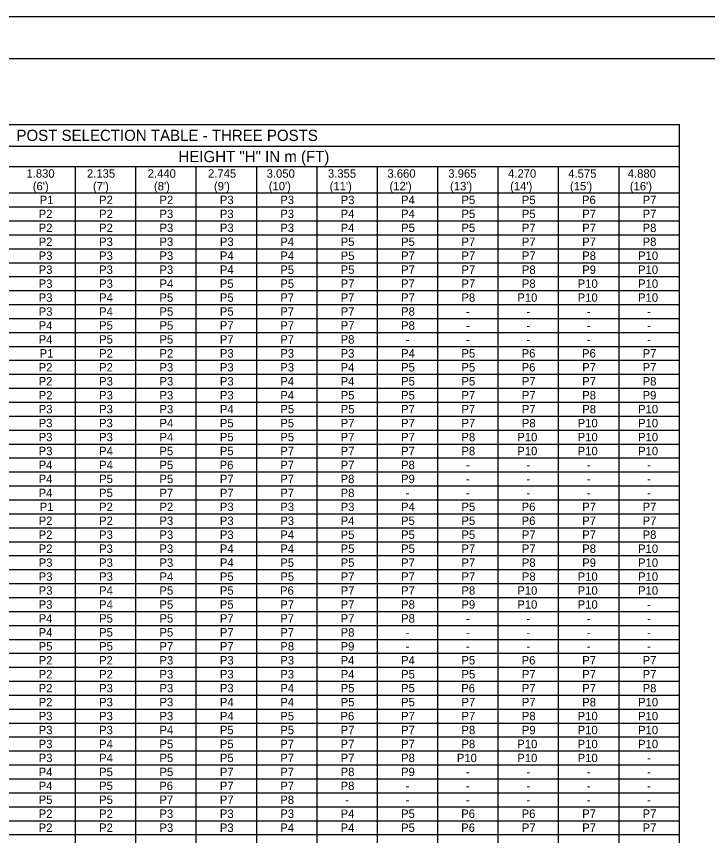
# Model space of a CAD drawing. Extents: x 637580 to 641008, y 294594 to 295782.
# Drawn here: x 640290.4 to 640536.7, y 295489.6 to 295781.6 of the extents above; entities that cross this region are included whole.
import ezdxf

# ---------------------------------------------------------------- set-up
doc = ezdxf.new("R2010")
doc.units = 0
for name, color, linetype in [('1', 7, 'Continuous'), ('2', 7, 'Continuous'), ('PLT-BNDY', 7, 'Continuous')]:
    doc.layers.add(name, color=color, linetype=linetype)

msp = doc.modelspace()

# ---------------------------------------------------------------- linework, layer by layer
at = {"layer": '1'}
for p, q in [((640143.31, 295766.63), (640929.31, 295766.63)), ((640191.43, 295743.08), (640526.66, 295743.08)), ((640526.66, 295226.43), (640526.66, 295743.08)), ((640191.43, 295735.41), (640526.66, 295735.41)), ((640191.43, 295718.7), (640526.66, 295718.7)), ((640191.43, 295664.01), (640526.66, 295664.01)), ((640191.43, 295609.31), (640526.66, 295609.31)), ((640191.43, 295554.61), (640526.66, 295554.61)), ((640191.43, 295499.91), (640526.66, 295499.91))]:
    msp.add_line(p, q, dxfattribs=at)
at = {"layer": '2'}
for p, q in [((640246.95, 295728.06), (640526.66, 295728.06)), ((640311.5, 295226.43), (640311.5, 295728.06)), ((640333.02, 295226.43), (640333.02, 295728.06)), ((640354.53, 295226.43), (640354.53, 295728.06)), ((640376.05, 295226.43), (640376.05, 295728.06)), ((640397.56, 295226.43), (640397.56, 295728.06)), ((640419.08, 295226.43), (640419.08, 295728.06)), ((640440.6, 295226.43), (640440.6, 295728.06)), ((640462.11, 295226.43), (640462.11, 295728.06)), ((640483.63, 295226.43), (640483.63, 295728.06)), ((640505.14, 295226.43), (640505.14, 295728.06)), ((640211.96, 295718.7), (640526.66, 295718.7)), ((640218.95, 295713.73), (640526.66, 295713.73)), ((640218.95, 295708.76), (640526.66, 295708.76)), ((640218.95, 295703.79), (640526.66, 295703.79)), ((640218.95, 295698.81), (640526.66, 295698.81)), ((640218.95, 295693.84), (640526.66, 295693.84)), ((640218.95, 295688.87), (640526.66, 295688.87)), ((640218.95, 295683.9), (640526.66, 295683.9)), ((640218.95, 295678.92), (640526.66, 295678.92)), ((640218.95, 295673.95), (640526.66, 295673.95)), ((640218.95, 295668.98), (640526.66, 295668.98)), ((640218.95, 295659.03), (640526.66, 295659.03)), ((640218.95, 295654.06), (640526.66, 295654.06)), ((640218.95, 295649.09), (640526.66, 295649.09)), ((640218.95, 295644.12), (640526.66, 295644.12)), ((640218.95, 295639.14), (640526.66, 295639.14)), ((640218.95, 295634.17), (640526.66, 295634.17)), ((640218.95, 295629.2), (640526.66, 295629.2)), ((640218.95, 295624.23), (640526.66, 295624.23)), ((640218.95, 295619.25), (640526.66, 295619.25)), ((640218.95, 295614.28), (640526.66, 295614.28)), ((640218.95, 295604.34), (640526.66, 295604.34)), ((640218.95, 295599.36), (640526.66, 295599.36)), ((640218.95, 295594.39), (640526.66, 295594.39)), ((640218.95, 295589.42), (640526.66, 295589.42)), ((640218.95, 295584.45), (640526.66, 295584.45)), ((640218.95, 295579.47), (640526.66, 295579.47)), ((640218.95, 295574.5), (640526.66, 295574.5)), ((640218.95, 295569.53), (640526.66, 295569.53)), ((640218.95, 295564.56), (640526.66, 295564.56)), ((640218.95, 295559.58), (640526.66, 295559.58)), ((640218.95, 295549.64), (640526.66, 295549.64)), ((640218.95, 295544.67), (640526.66, 295544.67)), ((640218.95, 295539.69), (640526.66, 295539.69)), ((640218.95, 295534.72), (640526.66, 295534.72)), ((640218.95, 295529.75), (640526.66, 295529.75)), ((640218.95, 295524.78), (640526.66, 295524.78)), ((640218.95, 295519.8), (640526.66, 295519.8)), ((640218.95, 295514.83), (640526.66, 295514.83)), ((640218.95, 295509.86), (640526.66, 295509.86)), ((640218.95, 295504.89), (640526.66, 295504.89)), ((640218.95, 295494.94), (640526.66, 295494.94)), ((640218.95, 295489.97), (640526.66, 295489.97))]:
    msp.add_line(p, q, dxfattribs=at)
at = {"layer": 'PLT-BNDY'}
msp.add_lwpolyline([(640103.31, 295781.63), (640944.31, 295781.63), (640944.31, 295187.63), (640103.31, 295187.63)], close=True, dxfattribs=at)

# ---------------------------------------------------------------- texts
at = {"layer": '1'}
for s, height, p in [('POST SELECTION TABLE - THREE POSTS', 4.003, (640290.47, 295737.22)), ('HEIGHT "H" IN m (FT)', 4.003, (640348.19, 295729.67)), ('1.830', 3, (640294.03, 295724.12)), ('2.135', 3, (640315.59, 295724.12)), ('2.440', 3, (640337.22, 295724.12)), ('2.745', 3, (640358.71, 295724.12)), ('3.050', 3, (640379.6, 295724.12)), ('3.355', 3, (640401.43, 295724.12)), ('3.660', 3, (640422.63, 295724.12)), ('3.965', 3, (640444.31, 295724.12)), ('4.270', 3, (640465.6, 295724.12)), ('4.575', 3, (640487.05, 295724.12)), ('4.880', 3, (640508.25, 295724.12)), ("(6')", 3, (640296.28, 295719.62)), ("(7')", 3, (640317.71, 295719.62)), ("(8')", 3, (640339.47, 295719.62)), ("(9')", 3, (640360.83, 295719.62)), ("(10')", 3, (640380.34, 295719.62)), ("(11')", 3, (640402.05, 295719.62)), ("(12')", 3, (640423.37, 295719.62)), ("(13')", 3, (640444.93, 295719.62)), ("(14')", 3, (640466.34, 295719.62)), ("(15')", 3, (640487.67, 295719.62)), ("(16')", 3, (640508.99, 295719.62)), ('P1', 3, (640298.74, 295714.72)), ('P2', 3, (640319.91, 295714.72)), ('P2', 3, (640341.42, 295714.72)), ('P3', 3, (640362.94, 295714.72)), ('P3', 3, (640384.46, 295714.72)), ('P3', 3, (640405.97, 295714.71)), ('P4', 3, (640427.49, 295714.72)), ('P5', 3, (640449, 295714.72)), ('P5', 3, (640470.52, 295714.72)), ('P6', 3, (640491.95, 295714.72)), ('P7', 3, (640513.55, 295714.72)), ('P2', 3, (640298.39, 295709.74)), ('P2', 3, (640319.91, 295709.74)), ('P3', 3, (640341.42, 295709.74)), ('P3', 3, (640362.94, 295709.74)), ('P3', 3, (640384.46, 295709.74)), ('P4', 3, (640405.97, 295709.74)), ('P4', 3, (640427.49, 295709.74)), ('P5', 3, (640449, 295709.74)), ('P5', 3, (640470.52, 295709.74)), ('P7', 3, (640492.03, 295709.74)), ('P7', 3, (640513.55, 295709.74)), ('P2', 3, (640298.39, 295704.77)), ('P2', 3, (640319.91, 295704.77)), ('P3', 3, (640341.42, 295704.77)), ('P3', 3, (640362.94, 295704.77)), ('P3', 3, (640384.46, 295704.77)), ('P4', 3, (640405.97, 295704.77)), ('P5', 3, (640427.49, 295704.77)), ('P5', 3, (640449, 295704.77)), ('P7', 3, (640470.52, 295704.77)), ('P7', 3, (640492.03, 295704.77)), ('P8', 3, (640513.55, 295704.77)), ('P2', 3, (640298.39, 295699.8)), ('P3', 3, (640319.91, 295699.8)), ('P3', 3, (640341.42, 295699.8)), ('P3', 3, (640362.94, 295699.8)), ('P4', 3, (640384.46, 295699.8)), ('P5', 3, (640405.97, 295699.79)), ('P5', 3, (640427.49, 295699.8)), ('P7', 3, (640449, 295699.8)), ('P7', 3, (640470.52, 295699.8)), ('P7', 3, (640492.03, 295699.8)), ('P8', 3, (640513.55, 295699.8)), ('P3', 3, (640298.39, 295694.83)), ('P3', 3, (640319.91, 295694.83)), ('P3', 3, (640341.42, 295694.83)), ('P4', 3, (640362.94, 295694.83)), ('P4', 3, (640384.46, 295694.83)), ('P5', 3, (640405.97, 295694.82)), ('P7', 3, (640427.49, 295694.83)), ('P7', 3, (640449, 295694.83)), ('P7', 3, (640470.52, 295694.83)), ('P8', 3, (640492.03, 295694.83)), ('P10', 3, (640511.92, 295694.83)), ('P3', 3, (640298.39, 295689.85)), ('P3', 3, (640319.91, 295689.85)), ('P3', 3, (640341.42, 295689.85)), ('P4', 3, (640362.94, 295689.85)), ('P5', 3, (640384.46, 295689.85)), ('P5', 3, (640405.97, 295689.85)), ('P7', 3, (640427.49, 295689.85)), ('P7', 3, (640449, 295689.85)), ('P8', 3, (640470.52, 295689.85)), ('P9', 3, (640492.02, 295689.85)), ('P10', 3, (640511.92, 295689.85)), ('P3', 3, (640298.39, 295684.88)), ('P3', 3, (640319.91, 295684.88)), ('P4', 3, (640341.42, 295684.88)), ('P5', 3, (640362.94, 295684.88)), ('P5', 3, (640384.46, 295684.88)), ('P7', 3, (640405.97, 295684.88)), ('P7', 3, (640427.49, 295684.88)), ('P7', 3, (640449, 295684.88)), ('P8', 3, (640470.52, 295684.88)), ('P10', 3, (640490.4, 295684.88)), ('P10', 3, (640511.92, 295684.88)), ('P3', 3, (640298.39, 295679.91)), ('P4', 3, (640319.91, 295679.91)), ('P5', 3, (640341.42, 295679.91)), ('P5', 3, (640362.94, 295679.91)), ('P7', 3, (640384.46, 295679.91)), ('P7', 3, (640405.97, 295679.9)), ('P7', 3, (640427.49, 295679.91)), ('P8', 3, (640449, 295679.91)), ('P10', 3, (640468.89, 295679.91)), ('P10', 3, (640490.4, 295679.91)), ('P10', 3, (640511.92, 295679.91)), ('P3', 3, (640298.39, 295674.94)), ('P4', 3, (640319.91, 295674.94)), ('P5', 3, (640341.42, 295674.94)), ('P5', 3, (640362.94, 295674.94)), ('P7', 3, (640384.46, 295674.94)), ('P7', 3, (640405.97, 295674.93)), ('P8', 3, (640427.49, 295674.94)), ('-', 3, (640450.62, 295674.94)), ('-', 3, (640472.14, 295674.94)), ('-', 3, (640493.65, 295674.94)), ('-', 3, (640515.17, 295674.94)), ('P4', 3, (640298.39, 295669.96)), ('P5', 3, (640319.91, 295669.96)), ('P5', 3, (640341.42, 295669.96)), ('P7', 3, (640362.94, 295669.96)), ('P7', 3, (640384.46, 295669.96)), ('P7', 3, (640405.97, 295669.96)), ('P8', 3, (640427.49, 295669.96)), ('-', 3, (640450.62, 295669.96)), ('-', 3, (640472.14, 295669.96)), ('-', 3, (640493.65, 295669.96)), ('-', 3, (640515.17, 295669.96)), ('P4', 3, (640298.39, 295664.99)), ('P5', 3, (640319.91, 295664.99)), ('P5', 3, (640341.42, 295664.99)), ('P7', 3, (640362.94, 295664.99)), ('P7', 3, (640384.46, 295664.99)), ('P8', 3, (640405.97, 295664.99)), ('-', 3, (640429.11, 295664.99)), ('-', 3, (640450.62, 295664.99)), ('-', 3, (640472.14, 295664.99)), ('-', 3, (640493.65, 295664.99)), ('-', 3, (640515.17, 295664.99)), ('P1', 3, (640298.74, 295660.02)), ('P2', 3, (640319.91, 295660.02)), ('P2', 3, (640341.42, 295660.02)), ('P3', 3, (640362.94, 295660.02)), ('P3', 3, (640384.46, 295660.02)), ('P3', 3, (640405.97, 295660.01)), ('P4', 3, (640427.49, 295660.02)), ('P5', 3, (640449, 295660.02)), ('P6', 3, (640470.44, 295660.02)), ('P6', 3, (640491.95, 295660.02)), ('P7', 3, (640513.55, 295660.02)), ('P2', 3, (640298.39, 295655.05)), ('P2', 3, (640319.91, 295655.05)), ('P3', 3, (640341.42, 295655.05)), ('P3', 3, (640362.94, 295655.05)), ('P3', 3, (640384.46, 295655.05)), ('P4', 3, (640405.97, 295655.04)), ('P5', 3, (640427.49, 295655.05)), ('P5', 3, (640449, 295655.05)), ('P6', 3, (640470.44, 295655.05)), ('P7', 3, (640492.03, 295655.05)), ('P7', 3, (640513.55, 295655.05)), ('P2', 3, (640298.39, 295650.07)), ('P3', 3, (640319.91, 295650.07)), ('P3', 3, (640341.42, 295650.07)), ('P3', 3, (640362.94, 295650.07)), ('P4', 3, (640384.46, 295650.07)), ('P4', 3, (640405.97, 295650.07)), ('P5', 3, (640427.49, 295650.07)), ('P5', 3, (640449, 295650.07)), ('P7', 3, (640470.52, 295650.07)), ('P7', 3, (640492.03, 295650.07)), ('P8', 3, (640513.55, 295650.07)), ('P2', 3, (640298.39, 295645.1)), ('P3', 3, (640319.91, 295645.1)), ('P3', 3, (640341.42, 295645.1)), ('P3', 3, (640362.94, 295645.1)), ('P4', 3, (640384.46, 295645.1)), ('P5', 3, (640405.97, 295645.1)), ('P5', 3, (640427.49, 295645.1)), ('P7', 3, (640449, 295645.1)), ('P7', 3, (640470.52, 295645.1)), ('P8', 3, (640492.03, 295645.1)), ('P9', 3, (640513.54, 295645.1)), ('P3', 3, (640298.39, 295640.13)), ('P3', 3, (640319.91, 295640.13)), ('P3', 3, (640341.42, 295640.13)), ('P4', 3, (640362.94, 295640.13)), ('P5', 3, (640384.46, 295640.13)), ('P5', 3, (640405.97, 295640.12)), ('P7', 3, (640427.49, 295640.13)), ('P7', 3, (640449, 295640.13)), ('P7', 3, (640470.52, 295640.13)), ('P8', 3, (640492.03, 295640.13)), ('P10', 3, (640511.92, 295640.13)), ('P3', 3, (640298.39, 295635.16)), ('P3', 3, (640319.91, 295635.16)), ('P4', 3, (640341.42, 295635.16)), ('P5', 3, (640362.94, 295635.16)), ('P5', 3, (640384.46, 295635.16)), ('P7', 3, (640405.97, 295635.15)), ('P7', 3, (640427.49, 295635.16)), ('P7', 3, (640449, 295635.16)), ('P8', 3, (640470.52, 295635.16)), ('P10', 3, (640490.4, 295635.16)), ('P10', 3, (640511.92, 295635.16)), ('P3', 3, (640298.39, 295630.18)), ('P3', 3, (640319.91, 295630.18)), ('P8', 3, (640449, 295630.18)), ('P10', 3, (640468.89, 295630.18)), ('P10', 3, (640490.4, 295630.18)), ('P10', 3, (640511.92, 295630.18)), ('P4', 3, (640341.42, 295630.18)), ('P5', 3, (640362.94, 295630.18)), ('P5', 3, (640384.46, 295630.18)), ('P7', 3, (640405.97, 295630.18)), ('P7', 3, (640427.49, 295630.18)), ('P3', 3, (640298.39, 295625.21)), ('P4', 3, (640319.91, 295625.21)), ('P5', 3, (640341.42, 295625.21)), ('P5', 3, (640362.94, 295625.21)), ('P7', 3, (640384.46, 295625.21)), ('P7', 3, (640405.97, 295625.21)), ('P7', 3, (640427.49, 295625.21)), ('P8', 3, (640449, 295625.21)), ('P10', 3, (640468.89, 295625.21)), ('P10', 3, (640490.4, 295625.21)), ('P10', 3, (640511.92, 295625.21)), ('P4', 3, (640298.39, 295620.24)), ('P4', 3, (640319.91, 295620.24)), ('P5', 3, (640341.42, 295620.24)), ('P6', 3, (640362.86, 295620.24)), ('P7', 3, (640384.46, 295620.24)), ('P7', 3, (640405.97, 295620.23)), ('P8', 3, (640427.49, 295620.24)), ('-', 3, (640450.62, 295620.24)), ('-', 3, (640472.14, 295620.24)), ('-', 3, (640493.65, 295620.24)), ('-', 3, (640515.17, 295620.24)), ('P4', 3, (640298.39, 295615.27)), ('P5', 3, (640319.91, 295615.27)), ('P5', 3, (640341.42, 295615.27)), ('P7', 3, (640362.94, 295615.27)), ('P7', 3, (640384.46, 295615.27)), ('P8', 3, (640405.97, 295615.26)), ('P9', 3, (640427.48, 295615.27)), ('-', 3, (640450.62, 295615.27)), ('-', 3, (640472.14, 295615.27)), ('-', 3, (640493.65, 295615.27)), ('-', 3, (640515.17, 295615.27)), ('P4', 3, (640298.39, 295610.29)), ('P5', 3, (640319.91, 295610.29)), ('P7', 3, (640341.42, 295610.29)), ('P7', 3, (640362.94, 295610.29)), ('P7', 3, (640384.46, 295610.29)), ('P8', 3, (640405.97, 295610.29)), ('-', 3, (640429.11, 295610.29)), ('-', 3, (640450.62, 295610.29)), ('-', 3, (640472.14, 295610.29)), ('-', 3, (640493.65, 295610.29)), ('-', 3, (640515.17, 295610.29)), ('P1', 3, (640298.74, 295605.32)), ('P2', 3, (640319.91, 295605.32)), ('P2', 3, (640341.42, 295605.32)), ('P3', 3, (640362.94, 295605.32)), ('P3', 3, (640384.46, 295605.32)), ('P3', 3, (640405.97, 295605.32)), ('P4', 3, (640427.49, 295605.32)), ('P5', 3, (640449, 295605.32)), ('P6', 3, (640470.44, 295605.32)), ('P7', 3, (640492.03, 295605.32)), ('P7', 3, (640513.55, 295605.32)), ('P2', 3, (640298.39, 295600.35)), ('P2', 3, (640319.91, 295600.35)), ('P3', 3, (640341.42, 295600.35)), ('P3', 3, (640362.94, 295600.35)), ('P3', 3, (640384.46, 295600.35)), ('P4', 3, (640405.97, 295600.34)), ('P5', 3, (640427.49, 295600.35)), ('P5', 3, (640449, 295600.35)), ('P6', 3, (640470.44, 295600.35)), ('P7', 3, (640492.03, 295600.35)), ('P7', 3, (640513.55, 295600.35)), ('P2', 3, (640298.39, 295595.38)), ('P3', 3, (640319.91, 295595.38)), ('P3', 3, (640341.42, 295595.38)), ('P3', 3, (640362.94, 295595.38)), ('P4', 3, (640384.46, 295595.38)), ('P5', 3, (640405.97, 295595.37)), ('P5', 3, (640427.49, 295595.38)), ('P5', 3, (640449, 295595.38)), ('P7', 3, (640470.52, 295595.38)), ('P7', 3, (640492.03, 295595.38)), ('P8', 3, (640513.55, 295595.38)), ('P2', 3, (640298.39, 295590.4)), ('P3', 3, (640319.91, 295590.4)), ('P3', 3, (640341.42, 295590.4)), ('P4', 3, (640362.94, 295590.4)), ('P4', 3, (640384.46, 295590.4)), ('P5', 3, (640405.97, 295590.4)), ('P5', 3, (640427.49, 295590.4)), ('P7', 3, (640449, 295590.4)), ('P7', 3, (640470.52, 295590.4)), ('P8', 3, (640492.03, 295590.4)), ('P10', 3, (640511.92, 295590.4)), ('P3', 3, (640298.39, 295585.43)), ('P3', 3, (640319.91, 295585.43)), ('P3', 3, (640341.42, 295585.43)), ('P4', 3, (640362.94, 295585.43)), ('P5', 3, (640384.46, 295585.43)), ('P5', 3, (640405.97, 295585.43)), ('P7', 3, (640427.49, 295585.43)), ('P7', 3, (640449, 295585.43)), ('P8', 3, (640470.52, 295585.43)), ('P9', 3, (640492.02, 295585.43)), ('P10', 3, (640511.92, 295585.43)), ('P3', 3, (640298.39, 295580.46)), ('P3', 3, (640319.91, 295580.46)), ('P4', 3, (640341.42, 295580.46)), ('P5', 3, (640362.94, 295580.46)), ('P5', 3, (640384.46, 295580.46)), ('P7', 3, (640405.97, 295580.45)), ('P7', 3, (640427.49, 295580.46)), ('P7', 3, (640449, 295580.46)), ('P8', 3, (640470.52, 295580.46)), ('P10', 3, (640490.4, 295580.46)), ('P10', 3, (640511.92, 295580.46)), ('P3', 3, (640298.39, 295575.49)), ('P4', 3, (640319.91, 295575.49)), ('P5', 3, (640341.42, 295575.49)), ('P5', 3, (640362.94, 295575.49)), ('P6', 3, (640384.37, 295575.49)), ('P7', 3, (640405.97, 295575.48)), ('P7', 3, (640427.49, 295575.49)), ('P8', 3, (640449, 295575.49)), ('P10', 3, (640468.89, 295575.49)), ('P10', 3, (640490.4, 295575.49)), ('P10', 3, (640511.92, 295575.49)), ('P3', 3, (640298.39, 295570.51)), ('P4', 3, (640319.91, 295570.51)), ('P5', 3, (640341.42, 295570.51)), ('P5', 3, (640362.94, 295570.51)), ('P7', 3, (640384.46, 295570.51)), ('P7', 3, (640405.97, 295570.51)), ('P8', 3, (640427.49, 295570.51)), ('P9', 3, (640448.99, 295570.51)), ('P10', 3, (640468.89, 295570.51)), ('P10', 3, (640490.4, 295570.51)), ('-', 3, (640515.17, 295570.51)), ('P4', 3, (640298.39, 295565.54)), ('P5', 3, (640319.91, 295565.54)), ('P5', 3, (640341.42, 295565.54)), ('P7', 3, (640362.94, 295565.54)), ('P7', 3, (640384.46, 295565.54)), ('P7', 3, (640405.97, 295565.54)), ('P8', 3, (640427.49, 295565.54)), ('-', 3, (640450.62, 295565.54)), ('-', 3, (640472.14, 295565.54)), ('-', 3, (640493.65, 295565.54)), ('-', 3, (640515.17, 295565.54)), ('P4', 3, (640298.39, 295560.57)), ('P5', 3, (640319.91, 295560.57)), ('P5', 3, (640341.42, 295560.57)), ('P7', 3, (640362.94, 295560.57)), ('P7', 3, (640384.46, 295560.57)), ('P8', 3, (640405.97, 295560.56)), ('-', 3, (640429.11, 295560.57)), ('-', 3, (640450.62, 295560.57)), ('-', 3, (640472.14, 295560.57)), ('-', 3, (640493.65, 295560.57)), ('-', 3, (640515.17, 295560.57)), ('P5', 3, (640298.39, 295555.6)), ('P5', 3, (640319.91, 295555.6)), ('P7', 3, (640341.42, 295555.6)), ('P7', 3, (640362.94, 295555.6)), ('P8', 3, (640384.46, 295555.6)), ('P9', 3, (640405.96, 295555.59)), ('-', 3, (640429.11, 295555.6)), ('-', 3, (640450.62, 295555.6)), ('-', 3, (640472.14, 295555.6)), ('-', 3, (640493.65, 295555.6)), ('-', 3, (640515.17, 295555.6)), ('P2', 3, (640298.39, 295550.62)), ('P2', 3, (640319.91, 295550.62)), ('P3', 3, (640341.42, 295550.62)), ('P3', 3, (640362.94, 295550.62)), ('P3', 3, (640384.46, 295550.62)), ('P4', 3, (640405.97, 295550.62)), ('P4', 3, (640427.49, 295550.62)), ('P5', 3, (640449, 295550.62)), ('P6', 3, (640470.44, 295550.62)), ('P7', 3, (640492.03, 295550.62)), ('P7', 3, (640513.55, 295550.62)), ('P2', 3, (640298.39, 295545.65)), ('P2', 3, (640319.91, 295545.65)), ('P3', 3, (640341.42, 295545.65)), ('P3', 3, (640362.94, 295545.65)), ('P3', 3, (640384.46, 295545.65)), ('P4', 3, (640405.97, 295545.65)), ('P5', 3, (640427.49, 295545.65)), ('P5', 3, (640449, 295545.65)), ('P7', 3, (640470.52, 295545.65)), ('P7', 3, (640492.03, 295545.65)), ('P7', 3, (640513.55, 295545.65)), ('P2', 3, (640298.39, 295540.68)), ('P3', 3, (640319.91, 295540.68)), ('P3', 3, (640341.42, 295540.68)), ('P3', 3, (640362.94, 295540.68)), ('P4', 3, (640384.46, 295540.68)), ('P5', 3, (640405.97, 295540.67)), ('P5', 3, (640427.49, 295540.68)), ('P6', 3, (640448.92, 295540.68)), ('P7', 3, (640470.52, 295540.68)), ('P7', 3, (640492.03, 295540.68)), ('P8', 3, (640513.55, 295540.68)), ('P2', 3, (640298.39, 295535.71)), ('P3', 3, (640319.91, 295535.71)), ('P3', 3, (640341.42, 295535.71)), ('P4', 3, (640362.94, 295535.71)), ('P4', 3, (640384.46, 295535.71)), ('P5', 3, (640405.97, 295535.7)), ('P5', 3, (640427.49, 295535.71)), ('P7', 3, (640449, 295535.71)), ('P7', 3, (640470.52, 295535.71)), ('P8', 3, (640492.03, 295535.71)), ('P10', 3, (640511.92, 295535.71)), ('P3', 3, (640298.39, 295530.73)), ('P3', 3, (640319.91, 295530.73)), ('P3', 3, (640341.42, 295530.73)), ('P4', 3, (640362.94, 295530.73)), ('P5', 3, (640384.46, 295530.73)), ('P6', 3, (640405.89, 295530.73)), ('P7', 3, (640427.49, 295530.73)), ('P7', 3, (640449, 295530.73)), ('P8', 3, (640470.52, 295530.73)), ('P10', 3, (640490.4, 295530.73)), ('P10', 3, (640511.92, 295530.73)), ('P3', 3, (640298.39, 295525.76)), ('P3', 3, (640319.91, 295525.76)), ('P4', 3, (640341.42, 295525.76)), ('P5', 3, (640362.94, 295525.76)), ('P5', 3, (640384.46, 295525.76)), ('P7', 3, (640405.97, 295525.76)), ('P7', 3, (640427.49, 295525.76)), ('P8', 3, (640449, 295525.76)), ('P9', 3, (640470.51, 295525.76)), ('P10', 3, (640490.4, 295525.76)), ('P10', 3, (640511.92, 295525.76)), ('P3', 3, (640298.39, 295520.79)), ('P4', 3, (640319.91, 295520.79)), ('P5', 3, (640341.42, 295520.79)), ('P5', 3, (640362.94, 295520.79)), ('P7', 3, (640384.46, 295520.79)), ('P7', 3, (640405.97, 295520.78)), ('P7', 3, (640427.49, 295520.79)), ('P8', 3, (640449, 295520.79)), ('P10', 3, (640468.89, 295520.79)), ('P10', 3, (640490.4, 295520.79)), ('P10', 3, (640511.92, 295520.79)), ('P3', 3, (640298.39, 295515.82)), ('P4', 3, (640319.91, 295515.82)), ('P5', 3, (640341.42, 295515.82)), ('P5', 3, (640362.94, 295515.82)), ('P7', 3, (640384.46, 295515.82)), ('P7', 3, (640405.97, 295515.81)), ('P8', 3, (640427.49, 295515.82)), ('P10', 3, (640447.37, 295515.82)), ('P10', 3, (640468.89, 295515.82)), ('P10', 3, (640490.4, 295515.82)), ('-', 3, (640515.17, 295515.82)), ('P4', 3, (640298.39, 295510.84)), ('P5', 3, (640319.91, 295510.84)), ('P5', 3, (640341.42, 295510.84)), ('P7', 3, (640362.94, 295510.84)), ('P7', 3, (640384.46, 295510.84)), ('P8', 3, (640405.97, 295510.84)), ('P9', 3, (640427.48, 295510.84)), ('-', 3, (640450.62, 295510.84)), ('-', 3, (640472.14, 295510.84)), ('-', 3, (640493.65, 295510.84)), ('-', 3, (640515.17, 295510.84)), ('P4', 3, (640298.39, 295505.87)), ('P5', 3, (640319.91, 295505.87)), ('P6', 3, (640341.34, 295505.87)), ('P7', 3, (640362.94, 295505.87)), ('P7', 3, (640384.46, 295505.87)), ('P8', 3, (640405.97, 295505.87)), ('-', 3, (640429.11, 295505.87)), ('-', 3, (640450.62, 295505.87)), ('-', 3, (640472.14, 295505.87)), ('-', 3, (640493.65, 295505.87)), ('-', 3, (640515.17, 295505.87)), ('P5', 3, (640298.39, 295500.9)), ('P5', 3, (640319.91, 295500.9)), ('P7', 3, (640341.42, 295500.9)), ('P7', 3, (640362.94, 295500.9)), ('P8', 3, (640384.46, 295500.9)), ('-', 3, (640407.59, 295500.89)), ('-', 3, (640429.11, 295500.9)), ('-', 3, (640450.62, 295500.9)), ('-', 3, (640472.14, 295500.9)), ('-', 3, (640493.65, 295500.9)), ('-', 3, (640515.17, 295500.9)), ('P2', 3, (640298.39, 295495.93)), ('P2', 3, (640319.91, 295495.93)), ('P3', 3, (640341.42, 295495.93)), ('P3', 3, (640362.94, 295495.93)), ('P3', 3, (640384.46, 295495.93)), ('P4', 3, (640405.97, 295495.92)), ('P5', 3, (640427.49, 295495.93)), ('P6', 3, (640448.92, 295495.93)), ('P6', 3, (640470.44, 295495.93)), ('P7', 3, (640492.03, 295495.93)), ('P7', 3, (640513.55, 295495.93)), ('P2', 3, (640298.39, 295490.95)), ('P2', 3, (640319.91, 295490.95)), ('P3', 3, (640341.42, 295490.95)), ('P3', 3, (640362.94, 295490.95)), ('P4', 3, (640384.46, 295490.95)), ('P4', 3, (640405.97, 295490.95)), ('P5', 3, (640427.49, 295490.95)), ('P6', 3, (640448.92, 295490.95)), ('P7', 3, (640470.52, 295490.95)), ('P7', 3, (640492.03, 295490.95)), ('P7', 3, (640513.55, 295490.95))]:
    msp.add_text(s, height=height, dxfattribs=at).set_placement(p)

doc.saveas('drawing.dxf')
